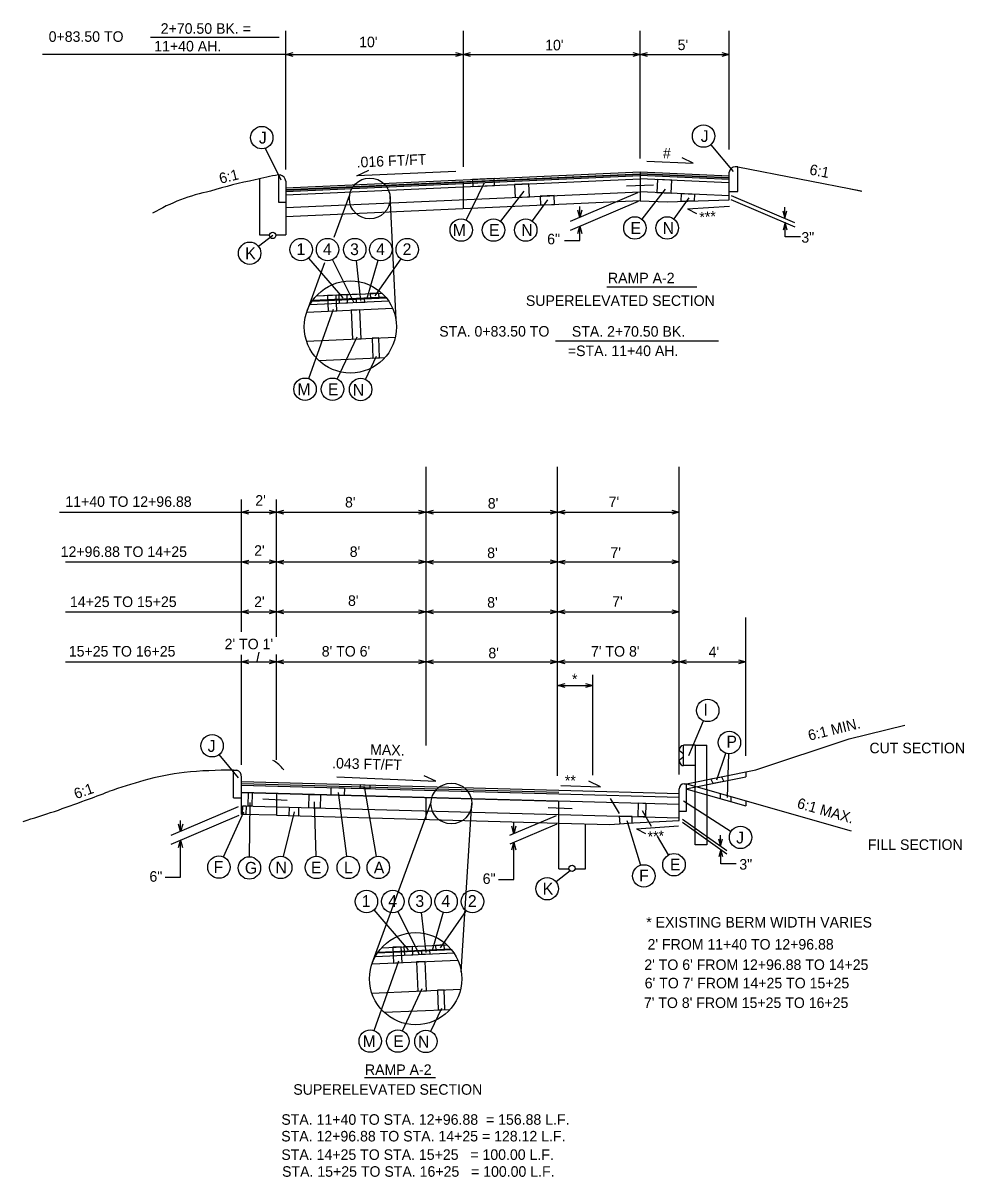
# Model space of a CAD drawing. Extents: x -210 to 558, y -150 to 205.
# Drawn here: x 282.7 to 336.2, y 19.8 to 85.5 of the extents above; entities that cross this region are included whole.
import ezdxf

# ---------------------------------------------------------------- set-up
doc = ezdxf.new("R2010")
doc.units = 0
for name, color, linetype in [('Level 4', 7, 'Continuous'), ('Level 59', 7, 'Continuous'), ('Level 6', 7, 'Continuous'), ('Level 60', 7, 'Continuous'), ('Level 7', 7, 'Continuous')]:
    doc.layers.add(name, color=color, linetype=linetype)

msp = doc.modelspace()

# ---------------------------------------------------------------- linework, layer by layer
at = {"layer": 'Level 4'}
for p, q in [((297.636, 77.127), (297.636, 85.028)), ((307.714, 85.028), (307.714, 77.278)), ((317.793, 77.752), (317.793, 85.028)), ((322.854, 78.267), (322.854, 85.028)), ((289.929, 84.657), (297.26, 84.657)), ((297.636, 83.67), (283.79, 83.67)), ((297.636, 83.67), (307.714, 83.67)), ((307.714, 83.67), (317.793, 83.67)), ((317.793, 83.67), (322.854, 83.67)), ((322.854, 78.267), (322.854, 81.854)), ((318.174, 77.605), (320.807, 77.487)), ((320.807, 77.487), (320.175, 77.791)), ((301.682, 76.762), (302.347, 77.082)), ((307.308, 77.014), (301.682, 76.762)), ((317.635, 75.795), (313.799, 74.163)), ((322.969, 75.649), (326.573, 74.115)), ((317.667, 75.312), (313.799, 73.666)), ((314.354, 74.399), (314.354, 75.028)), ((320.486, 74.881), (322.879, 75.051)), ((320.486, 74.881), (321, 74.616)), ((322.938, 75.42), (326.583, 73.869)), ((326.019, 74.351), (326.019, 74.98)), ((314.354, 73.087), (314.354, 73.902)), ((326.029, 73.29), (326.029, 74.105)), ((313.478, 73.087), (314.354, 73.087)), ((326.905, 73.29), (326.029, 73.29)), ((315.897, 70.447), (321.006, 70.447)), ((312.981, 67.375), (322.251, 67.375)), ((305.608, 44.352), (305.608, 60.209)), ((313.096, 42.619), (313.096, 60.209)), ((320.006, 42.692), (320.006, 60.209)), ((295.108, 50.827), (295.108, 58.351)), ((297.108, 50.54), (297.108, 58.351)), ((284.761, 57.633), (295.108, 57.633)), ((295.108, 57.633), (297.108, 57.633)), ((297.108, 57.633), (305.608, 57.633)), ((305.461, 57.651), (305.878, 57.651)), ((305.608, 57.633), (313.096, 57.633)), ((313.096, 57.633), (320.006, 57.633)), ((285.093, 54.794), (295.108, 54.794)), ((295.108, 54.794), (297.108, 54.794)), ((297.108, 54.794), (305.608, 54.794)), ((305.461, 54.812), (305.878, 54.812)), ((305.608, 54.794), (313.096, 54.794)), ((313.096, 54.794), (320.006, 54.794)), ((285.093, 51.955), (295.108, 51.955)), ((295.108, 51.955), (297.108, 51.955)), ((297.108, 51.955), (305.608, 51.955)), ((305.461, 51.973), (305.878, 51.973)), ((305.608, 51.955), (313.096, 51.955)), ((313.096, 51.955), (320.006, 51.955)), ((297.108, 51.195), (297.108, 51.585)), ((323.796, 43.769), (323.796, 51.636)), ((295.108, 43.247), (295.108, 49.505)), ((296.096, 49.671), (295.983, 49.123)), ((297.108, 43.542), (297.108, 49.527)), ((285.093, 49.116), (295.108, 49.116)), ((295.108, 49.116), (297.108, 49.116)), ((297.108, 49.116), (305.608, 49.116)), ((305.461, 49.134), (305.878, 49.134)), ((305.608, 49.116), (313.096, 49.116)), ((313.096, 49.116), (323.796, 49.116)), ((315.096, 42.666), (315.096, 48.363)), ((313.096, 47.762), (315.096, 47.762)), ((300.543, 42.564), (306.168, 42.312)), ((306.168, 42.312), (305.503, 42.632)), ((313.275, 42.082), (315.533, 41.998)), ((315.533, 41.998), (314.868, 42.318)), ((294.931, 40.852), (291.095, 39.22)), ((294.963, 40.369), (291.095, 38.723)), ((291.65, 39.456), (291.65, 40.086)), ((313.013, 40.355), (310.351, 39.222)), ((320.197, 40.162), (322.718, 38.375)), ((313.045, 39.872), (310.375, 38.735)), ((310.606, 39.331), (310.606, 39.96)), ((317.583, 39.606), (319.976, 39.776)), ((317.583, 39.606), (318.097, 39.341)), ((320.197, 39.98), (322.727, 38.188)), ((291.65, 36.86), (291.65, 38.959)), ((310.606, 36.734), (310.606, 38.834)), ((322.363, 38.625), (322.363, 39.255)), ((322.373, 37.625), (322.373, 38.44)), ((323.249, 37.625), (322.373, 37.625)), ((290.774, 36.86), (291.65, 36.86)), ((309.73, 36.734), (310.606, 36.734)), ((302.102, 25.459), (306.156, 25.459))]:
    msp.add_line(p, q, dxfattribs=at)
for points in [[(298.056, 83.554), (297.636, 83.67), (298.056, 83.782)], [(307.294, 83.786), (307.714, 83.67), (307.294, 83.558)], [(308.134, 83.554), (307.714, 83.67), (308.134, 83.782)], [(317.373, 83.786), (317.793, 83.67), (317.373, 83.558)], [(318.213, 83.554), (317.793, 83.67), (318.213, 83.782)], [(322.434, 83.786), (322.854, 83.67), (322.434, 83.558)], [(314.47, 74.819), (314.354, 74.399), (314.242, 74.819)], [(325.903, 74.771), (326.019, 74.351), (326.131, 74.771)], [(314.238, 73.482), (314.354, 73.902), (314.466, 73.482)], [(326.145, 73.685), (326.029, 74.105), (325.917, 73.685)], [(295.528, 57.517), (295.108, 57.633), (295.528, 57.745)], [(296.688, 57.749), (297.108, 57.633), (296.688, 57.521)], [(297.528, 57.517), (297.108, 57.633), (297.528, 57.745)], [(305.188, 57.749), (305.608, 57.633), (305.188, 57.521)], [(306.028, 57.517), (305.608, 57.633), (306.028, 57.745)], [(312.676, 57.749), (313.096, 57.633), (312.676, 57.521)], [(313.516, 57.517), (313.096, 57.633), (313.516, 57.745)], [(319.586, 57.749), (320.006, 57.633), (319.586, 57.521)], [(295.528, 54.678), (295.108, 54.794), (295.528, 54.906)], [(296.688, 54.91), (297.108, 54.794), (296.688, 54.682)], [(297.528, 54.678), (297.108, 54.794), (297.528, 54.906)], [(305.188, 54.91), (305.608, 54.794), (305.188, 54.682)], [(306.028, 54.678), (305.608, 54.794), (306.028, 54.906)], [(312.676, 54.91), (313.096, 54.794), (312.676, 54.682)], [(313.516, 54.678), (313.096, 54.794), (313.516, 54.906)], [(319.586, 54.91), (320.006, 54.794), (319.586, 54.682)], [(295.528, 51.839), (295.108, 51.955), (295.528, 52.067)], [(296.688, 52.071), (297.108, 51.955), (296.688, 51.843)], [(297.528, 51.839), (297.108, 51.955), (297.528, 52.067)], [(305.188, 52.071), (305.608, 51.955), (305.188, 51.843)], [(306.028, 51.839), (305.608, 51.955), (306.028, 52.067)], [(312.676, 52.071), (313.096, 51.955), (312.676, 51.843)], [(313.516, 51.839), (313.096, 51.955), (313.516, 52.067)], [(319.586, 52.071), (320.006, 51.955), (319.586, 51.843)], [(295.528, 49), (295.108, 49.116), (295.528, 49.228)], [(296.688, 49.232), (297.108, 49.116), (296.688, 49.004)], [(297.528, 49), (297.108, 49.116), (297.528, 49.228)], [(305.188, 49.232), (305.608, 49.116), (305.188, 49.004)], [(306.028, 49), (305.608, 49.116), (306.028, 49.228)], [(312.676, 49.232), (313.096, 49.116), (312.676, 49.004)], [(313.516, 49), (313.096, 49.116), (313.516, 49.228)], [(319.586, 49.232), (320.006, 49.116), (319.586, 49.004)], [(320.426, 49), (320.006, 49.116), (320.426, 49.228)], [(323.376, 49.232), (323.796, 49.116), (323.376, 49.004)], [(313.516, 47.646), (313.096, 47.762), (313.516, 47.874)], [(314.676, 47.878), (315.096, 47.762), (314.676, 47.65)], [(291.766, 39.876), (291.65, 39.456), (291.538, 39.876)], [(310.722, 39.751), (310.606, 39.331), (310.494, 39.751)], [(291.534, 38.539), (291.65, 38.959), (291.762, 38.539)], [(310.49, 38.414), (310.606, 38.834), (310.718, 38.414)], [(322.247, 39.045), (322.363, 38.625), (322.475, 39.045)], [(322.489, 38.02), (322.373, 38.44), (322.261, 38.02)]]:
    msp.add_lwpolyline(points, dxfattribs=at)
for points in [[(321.808, 42.449), (322.421, 42.569), (322.55, 42.308), (321.938, 42.188)], [(322.355, 41.615), (322.955, 41.445), (322.952, 41.153), (322.352, 41.323)]]:
    msp.add_lwpolyline(points, close=True, dxfattribs=at)
at = {"layer": 'Level 59'}
for p, q in [((296.466, 78.335), (297.354, 76.536)), ((321.805, 78.541), (323.077, 77.009)), ((308.925, 76.362), (307.894, 74.258)), ((311.169, 75.901), (309.838, 74.189)), ((319.214, 76.017), (317.883, 74.304)), ((320.556, 75.51), (319.698, 74.319)), ((312.511, 75.395), (311.653, 74.203)), ((296.886, 73.379), (296.081, 72.753)), ((298.925, 72.087), (300.885, 69.825)), ((300.293, 71.997), (301.498, 69.558)), ((301.628, 71.935), (301.888, 69.671)), ((302.863, 71.955), (302.245, 69.779)), ((304.176, 72.046), (302.702, 69.934)), ((298.939, 65.227), (300.342, 69.189)), ((300.561, 65.203), (301.685, 67.609)), ((302.165, 65.183), (302.797, 66.505)), ((320.554, 43.78), (321.386, 45.759)), ((294.934, 42.514), (293.844, 43.842)), ((322.143, 42.394), (322.658, 43.92)), ((322.749, 41.391), (322.839, 43.887)), ((301.105, 38.047), (300.633, 41.68)), ((302.788, 38.043), (302.115, 42.017)), ((295.568, 38.019), (295.609, 41.113)), ((299.359, 38.052), (299.272, 41.143)), ((320.257, 41.195), (322.96, 39.463)), ((294.094, 38.015), (295.247, 40.569)), ((297.497, 38.033), (298.126, 40.57)), ((317.022, 40.084), (317.807, 37.537)), ((317.901, 40.646), (318.419, 39.767)), ((318.753, 39.2), (319.389, 38.12)), ((313.811, 37.22), (313.005, 36.594)), ((302.637, 34.994), (304.597, 32.732)), ((304.005, 34.904), (305.21, 32.465)), ((305.34, 34.842), (305.6, 32.578)), ((306.575, 34.862), (305.958, 32.686)), ((307.888, 34.953), (306.414, 32.84)), ((302.651, 28.134), (304.054, 32.095)), ((304.273, 28.11), (305.397, 30.516)), ((305.877, 28.09), (306.509, 29.412))]:
    msp.add_line(p, q, dxfattribs=at)
for points in [[(308.266, 76.169), (309.509, 76.225), (309.491, 76.62), (308.248, 76.564)], [(310.682, 75.543), (311.491, 75.58), (311.458, 76.312), (310.649, 76.276)], [(318.742, 75.82), (319.555, 75.783), (319.588, 76.516), (318.775, 76.552)], [(312.118, 75.11), (312.914, 75.146), (312.892, 75.642), (312.096, 75.607)], [(320.128, 75.312), (320.142, 75.757), (320.875, 75.73), (320.875, 75.73), (320.869, 75.339)], [(300.05, 69.065), (300.535, 69.086), (300.488, 69.982), (300.003, 69.962)], [(300.664, 69.521), (301.148, 69.541), (301.128, 70.011), (300.643, 69.991)], [(301.641, 69.565), (302.126, 69.585), (302.117, 69.773), (301.632, 69.752)], [(302.453, 69.789), (302.938, 69.81), (302.924, 70.092), (302.44, 70.071)], [(301.434, 67.472), (301.918, 67.493), (301.84, 69.148), (301.356, 69.128)], [(302.591, 66.4), (302.969, 66.416), (302.921, 67.547), (302.543, 67.531)], [(295.485, 40.909), (295.506, 41.67), (295.718, 41.664), (295.697, 40.903)], [(295.178, 40.431), (295.191, 40.917), (295.372, 40.912), (295.359, 40.426)], [(303.763, 31.972), (304.247, 31.993), (304.2, 32.889), (303.716, 32.869)], [(304.376, 32.427), (304.86, 32.448), (304.84, 32.918), (304.355, 32.897)], [(306.166, 32.696), (306.65, 32.716), (306.636, 32.999), (306.152, 32.978)], [(305.353, 32.472), (305.838, 32.492), (305.829, 32.679), (305.345, 32.659)], [(305.146, 30.379), (305.63, 30.399), (305.553, 32.055), (305.068, 32.034)], [(306.303, 29.307), (306.681, 29.323), (306.633, 30.453), (306.256, 30.437)]]:
    msp.add_lwpolyline(points, close=True, dxfattribs=at)
for centre in [(296.264, 78.941), (321.397, 79.033), (307.613, 73.684), (309.446, 73.684), (311.279, 73.684), (317.491, 73.8), (319.325, 73.8), (295.576, 72.361), (298.506, 72.57), (300.01, 72.57), (301.555, 72.57), (303.038, 72.57), (304.542, 72.57), (298.725, 64.624), (300.29, 64.624), (301.89, 64.606), (321.633, 46.348), (293.439, 44.336), (322.863, 44.525), (323.502, 39.124), (319.714, 37.569), (293.831, 37.432), (295.56, 37.38), (297.343, 37.413), (299.377, 37.413), (301.187, 37.413), (302.895, 37.413), (317.995, 36.927), (312.5, 36.203), (302.218, 35.477), (303.722, 35.477), (305.267, 35.477), (306.75, 35.477), (308.254, 35.477), (302.437, 27.531), (304.003, 27.531), (305.602, 27.513)]:
    msp.add_circle(centre, 0.639, dxfattribs=at)
at = {"layer": 'Level 6'}
for p, q in [((297.636, 76.088), (317.793, 76.993)), ((297.636, 75.984), (317.793, 76.889)), ((317.793, 76.993), (317.793, 75.365)), ((322.852, 76.661), (317.793, 76.889)), ((322.852, 75.41), (322.852, 76.974)), ((323.352, 77.289), (323.192, 77.289)), ((323.352, 77.289), (330.37, 75.923)), ((323.352, 75.883), (323.352, 77.289)), ((296.131, 76.6), (296.131, 73.406)), ((297.213, 76.821), (297.213, 75.266)), ((297.213, 76.821), (297.304, 76.821)), ((297.636, 75.692), (317.793, 76.597)), ((297.636, 76.458), (297.636, 73.406)), ((307.714, 76.385), (307.714, 74.913)), ((317.003, 76.193), (318.544, 76.255)), ((322.841, 76.37), (317.793, 76.597)), ((297.636, 74.958), (317.793, 75.863)), ((322.852, 75.635), (317.791, 75.862)), ((322.852, 75.883), (323.352, 75.883)), ((329.487, 76.077), (330.405, 75.902)), ((297.213, 75.266), (297.636, 75.266)), ((297.636, 74.46), (317.793, 75.365)), ((317.791, 75.355), (319.32, 75.283)), ((319.32, 75.283), (322.852, 75.41)), ((296.131, 73.406), (296.706, 73.406)), ((297.067, 73.406), (297.636, 73.406)), ((299.17, 69.689), (303.303, 69.874)), ((299.366, 69.933), (301.829, 70.044)), ((298.824, 69.013), (303.707, 69.233)), ((298.815, 67.354), (303.865, 67.581)), ((299.509, 66.261), (303.272, 66.43)), ((329.683, 44.727), (332.849, 45.505)), ((324.361, 42.971), (329.683, 44.728)), ((320.019, 44.153), (320.167, 44.357)), ((320.224, 43.898), (320.034, 44.045)), ((320.167, 44.357), (320.254, 44.372)), ((320.92, 44.372), (320.254, 44.372)), ((320.254, 43.206), (320.254, 44.372)), ((320.92, 44.372), (320.92, 42.122)), ((320.92, 44.372), (321.587, 44.372)), ((321.587, 41.87), (321.587, 44.372)), ((320.167, 43.221), (320.019, 43.426)), ((320.034, 43.533), (320.224, 43.681)), ((294.659, 41.373), (294.659, 42.942)), ((294.659, 42.942), (294.843, 42.942)), ((320.167, 43.221), (320.254, 43.206)), ((320.92, 43.206), (320.254, 43.206)), ((320.417, 42.17), (324.361, 42.971)), ((323.796, 42.856), (323.796, 42.57)), ((295.108, 40.433), (295.108, 42.541)), ((295.108, 42.103), (313.169, 41.606)), ((320.288, 42.17), (320.417, 42.17)), ((320.394, 41.879), (323.796, 42.57)), ((320.417, 40.611), (320.417, 42.17)), ((320.417, 42.17), (329.786, 39.492)), ((320.92, 38.706), (320.92, 42.122)), ((294.659, 41.373), (295.108, 41.373)), ((295.108, 41.701), (313.128, 41.205)), ((295.108, 41.681), (313.169, 41.184)), ((297.108, 41.646), (297.108, 40.378)), ((305.608, 40.144), (305.608, 41.392)), ((313.169, 41.606), (320.006, 41.418)), ((320.006, 40.087), (320.006, 41.877)), ((320.394, 41.879), (323.804, 40.918)), ((321.587, 41.87), (321.587, 38.706)), ((295.108, 40.919), (297.108, 40.864)), ((296.328, 41.313), (297.705, 41.249)), ((297.108, 40.864), (313.169, 40.422)), ((312.552, 40.828), (313.928, 40.764)), ((313.128, 41.205), (320.006, 41.016)), ((313.169, 39.936), (313.169, 41.204)), ((323.804, 41.21), (323.804, 40.918)), ((297.108, 40.378), (295.108, 40.433)), ((297.108, 40.378), (313.169, 39.936)), ((313.169, 40.422), (320.006, 40.234)), ((317.406, 39.953), (320.006, 40.087)), ((320.006, 40.611), (320.417, 40.611)), ((313.169, 39.936), (316.061, 39.857)), ((313.169, 37.33), (313.169, 39.936)), ((314.679, 37.33), (314.679, 39.893)), ((316.061, 39.857), (317.406, 39.953)), ((321.587, 38.706), (320.92, 38.706)), ((313.169, 37.33), (313.734, 37.33)), ((314.093, 37.33), (314.679, 37.33)), ((303.078, 32.84), (305.541, 32.95)), ((302.882, 32.596), (307.015, 32.781)), ((302.537, 31.92), (307.419, 32.139)), ((302.528, 30.261), (307.577, 30.487)), ((303.221, 29.168), (306.984, 29.337))]:
    msp.add_line(p, q, dxfattribs=at)
for centre, radius in [((296.886, 73.379), 0.183), ((313.913, 37.357), 0.18)]:
    msp.add_circle(centre, radius, dxfattribs=at)
for centre, radius, start, end in [((323.233, 76.904), 0.387, 96.02749, 169.67861), ((301.771, 47.581), 29.551, 101.48467, 106.57547), ((300.376, 58.594), 18.499, 99.84483, 104.04247), ((297.237, 76.427), 0.4, 4.50116, 80.36352), ((295.49, 65.336), 10.774, 101.49358, 120.31113), ((320.082, 44.107), 0.0781, 144.08393, 232.1285), ((320.082, 43.471), 0.0781, 127.8715, 215.91607), ((320.176, 43.742), 0.0781, 307.8715, 360), ((294.03, 25.631), 17.325, 97.20085, 104.96984), ((294.39, 16.894), 26.049, 89.40827, 95.57705), ((294.75, 42.592), 0.361, 351.83326, 75.13882), ((306.616, -14.405), 59.281, 106.72669, 108.74418), ((320.294, 41.882), 0.287, 91.07893, 181.04781), ((277.368, 67.363), 27.585, 288.76299, 291.69708), ((269.556, 84.421), 46.288, 286.48159, 291.12853)]:
    msp.add_arc(centre, radius, start, end, dxfattribs=at)
at = {"layer": 'Level 60'}
for points in [[(301.867, 41.926), (301.872, 42.132), (302.41, 42.099), (302.405, 41.893)], [(298.933, 40.805), (298.954, 41.567), (299.614, 41.548), (299.593, 40.787)], [(300.204, 41.532), (300.218, 41.962), (300.964, 41.942), (300.95, 41.512)], [(297.822, 40.35), (297.835, 40.835), (298.362, 40.821), (298.348, 40.335)], [(317.68, 40.298), (317.702, 41.08), (318.11, 41.068), (318.089, 40.287)], [(316.629, 39.897), (317.334, 39.948), (317.334, 40.308), (316.604, 40.328)]]:
    msp.add_lwpolyline(points, close=True, dxfattribs=at)
at = {"layer": 'Level 7'}
for p, q in [((297.636, 76.088), (317.793, 76.993)), ((297.636, 75.962), (317.793, 76.867)), ((317.793, 76.993), (322.852, 76.766)), ((322.852, 76.64), (317.793, 76.867)), ((297.636, 75.879), (317.793, 76.784)), ((322.852, 76.557), (317.793, 76.784)), ((300.391, 73.281), (301.261, 75.649)), ((303.901, 68.568), (303.561, 75.631)), ((298.84, 69.058), (299.86, 71.836)), ((299.017, 69.446), (303.477, 69.647)), ((299.135, 69.639), (303.341, 69.828)), ((299.366, 69.933), (303.086, 70.1)), ((295.102, 42.1), (313.164, 41.604)), ((295.104, 42.184), (313.166, 41.687)), ((295.108, 42.309), (313.169, 41.812)), ((313.169, 41.812), (320.006, 41.624)), ((302.552, 31.965), (305.893, 41.117)), ((307.614, 31.475), (308.212, 41.076)), ((316.091, 41.342), (316.587, 40.486)), ((303.078, 32.839), (306.798, 33.006)), ((302.729, 32.353), (307.189, 32.553)), ((302.848, 32.546), (307.053, 32.735))]:
    msp.add_line(p, q, dxfattribs=at)
for centre, radius in [((302.409, 75.483), 1.161), ((301.309, 68.17), 2.623), ((307.051, 41.049), 1.161), ((305.021, 31.077), 2.623)]:
    msp.add_circle(centre, radius, dxfattribs=at)
msp.add_arc((295.958, 41.8), 1.947, 36.81944, 61.15971, dxfattribs=at)

# ---------------------------------------------------------------- texts
at = {"layer": 'Level 4'}
for s, p in [('2+70.50 BK. =', (290.518, 84.852)), ('0+83.50 TO', (284.143, 84.394)), ('11+40 AH.', (290.148, 83.848)), ("10'", (301.802, 84.088)), ("10'", (312.385, 83.908)), ("5'", (319.921, 83.922)), ('#', (319.087, 77.76)), ('3"', (326.958, 72.966)), ('6"', (312.501, 72.87)), ('RAMP A-2', (315.957, 70.655)), ('SUPERELEVATED SECTION', (311.291, 69.367)), ('STA. 0+83.50 TO', (306.36, 67.62)), ('STA. 2+70.50 BK. ', (313.903, 67.615)), ('=STA. 11+40 AH.', (313.678, 66.512)), ('11+40 TO 12+96.88', (285.093, 57.93)), ("2'", (295.897, 57.997)), ("8'", (301.001, 57.897)), ("8'", (309.122, 57.831)), ("7'", (315.999, 57.914)), ('12+96.88 TO 14+25', (284.828, 55.08)), ("2'", (295.831, 55.146)), ("8'", (301.267, 55.08)), ("8'", (309.088, 55.014)), ("7'", (316.098, 55.03)), ('14+25 TO 15+25', (285.355, 52.23)), ("2'", (295.831, 52.23)), ("8'", (301.17, 52.296)), ("8'", (309.088, 52.196)), ("7'", (316.197, 52.246)), ('15+25 TO 16+25', (285.289, 49.412)), ("2' TO 1'", (294.151, 49.826)), ("8' TO 6'", (299.676, 49.412)), ("8'", (309.155, 49.313)), ("7' TO 8'", (314.995, 49.41)), ("4'", (321.684, 49.374)), ('*', (313.909, 47.83)), ('CUT SECTION', (330.832, 43.908)), ('**', (313.505, 42.054)), ('FILL SECTION', (330.742, 38.411)), ('3"', (323.43, 37.287)), ('6"', (289.875, 36.599)), ('6"', (308.832, 36.474)), ('* EXISTING BERM WIDTH VARIES', (318.135, 33.992)), ("2' FROM 11+40 TO 12+96.88", (318.209, 32.737)), ("2' TO 6' FROM 12+96.88 TO 14+25", (318.024, 31.578)), ("6' TO 7' FROM 14+25 TO 15+25", (318.049, 30.531)), ("7' TO 8' FROM 15+25 TO 16+25", (318, 29.411)), ('RAMP A-2', (302.134, 25.603)), ('SUPERELEVATED SECTION', (298.06, 24.476)), ('STA. 11+40 TO STA. 12+96.88  = 156.88 L.F.', (297.378, 22.767)), ('STA. 12+96.88 TO STA. 14+25 = 128.12 L.F.', (297.373, 21.819)), ('STA. 14+25 TO STA. 15+25   = 100.00 L.F.', (297.38, 20.77)), ('STA. 15+25 TO STA. 16+25   = 100.00 L.F.', (297.421, 19.809))]:
    msp.add_text(s, height=0.6, dxfattribs=at).set_placement(p)
for s, rotation, p in [('.016 FT/FT', 2.57074, (301.674, 77.239)), ('6:1', 13.91866, (293.922, 76.313)), ('6:1', 348.97963, (327.386, 76.852)), ('***', 4.07739, (321.186, 74.107)), ('6:1 MIN.', 13.79506, (327.42, 44.622)), ('MAX.', 358.42591, (302.422, 43.826)), ('.043 FT/FT', 358.42591, (300.26, 43.054)), ('6:1', 19.53014, (285.707, 41.294)), ('6:1 MAX.', 344.04801, (326.671, 40.811)), ('***', 4.07739, (318.242, 38.855))]:
    msp.add_text(s, height=0.6, rotation=rotation, dxfattribs=at).set_placement(p)
at = {"layer": 'Level 59'}
for s, p in [('J', (296.099, 78.605)), ('J', (321.232, 78.697)), ('M', (307.131, 73.348)), ('E', (309.193, 73.348)), ('N', (311.026, 73.348)), ('E', (317.238, 73.463)), ('N', (319.071, 73.463)), ('1', (298.242, 72.257)), ('4', (299.746, 72.257)), ('3', (301.291, 72.257)), ('4', (302.774, 72.257)), ('2', (304.278, 72.257)), ('K', (295.322, 72.025)), ('M', (298.289, 64.286)), ('E', (300.031, 64.286)), ('N', (301.441, 64.255)), ('I', (321.39, 46.058)), ('J', (293.188, 43.989)), ('P', (322.697, 44.237)), ('J', (323.252, 38.777)), ('F', (293.525, 37.101)), ('G', (295.304, 37.055)), ('N', (297.047, 37.074)), ('E', (299.063, 37.074)), ('L', (300.944, 37.074)), ('A', (302.639, 37.074)), ('E', (319.485, 37.24)), ('F', (317.728, 36.621)), ('K', (312.247, 35.866)), ('1', (301.954, 35.164)), ('4', (303.458, 35.164)), ('3', (305.003, 35.164)), ('4', (306.486, 35.164)), ('2', (307.99, 35.164)), ('M', (302.002, 27.192)), ('E', (303.743, 27.192)), ('N', (305.153, 27.161))]:
    msp.add_text(s, height=0.67, dxfattribs=at).set_placement(p)

doc.saveas('drawing.dxf')
